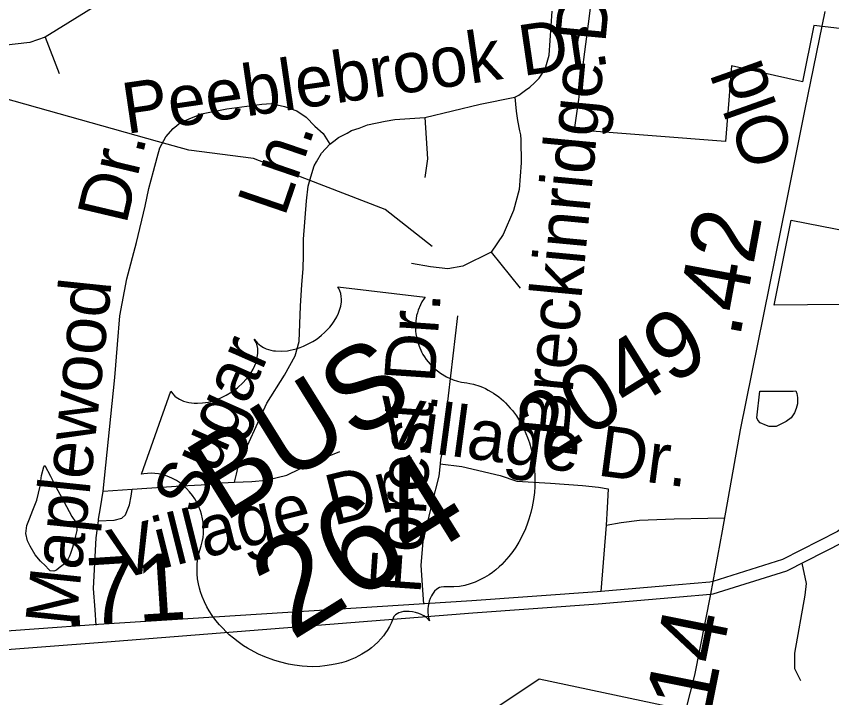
# Model space of a CAD drawing. Extents: x 2001466 to 31450019, y -30647475 to 847247.
# Drawn here: x 2153151 to 2156199, y 745745 to 748291 of the extents above; entities that cross this region are included whole.
import ezdxf

# ---------------------------------------------------------------- set-up
doc = ezdxf.new("R2010")
doc.units = 0
for name, color, linetype in [('Exist Boundary Political City Limit New', 7, 'Continuous'), ('Exist Hydrographic Misc Water Feature', 7, 'Continuous'), ('Exist Road Non-System Type 51', 7, 'Continuous'), ('Exist Road Non-System Type 51 Label', 7, 'Continuous'), ('Exist Road Primary US Divided Attributed', 7, 'Continuous'), ('Exist Road Primary US Mileage Hundredths English Label', 7, 'Continuous'), ('Exist Road Primary US Shield CELL', 7, 'Continuous'), ('Exist Road Primary US Shield Number Label', 7, 'Continuous'), ('Exist Road Secondary Mileage Hundredths English Label', 7, 'Continuous'), ('Exist Road Secondary Type 51 Attributed', 7, 'Continuous'), ('Exist Road Secondary Type 51 Label', 7, 'Continuous'), ('Exist Road Secondary Type 51 Number Label', 7, 'Continuous'), ('Exist Utilities Electrical Transmission Line', 7, 'Continuous'), ('Map Preparation Boundary City Limit Buffer Line', 7, 'Continuous')]:
    doc.layers.add(name, color=color, linetype=linetype)

msp = doc.modelspace()

# ---------------------------------------------------------------- linework, layer by layer
at = {"layer": 'Exist Boundary Political City Limit New'}
for points in [[(2156653.8, 748195.6), (2156132.8, 748257.3), (2156090.5, 748046.9), (2156085.5, 748047.9), (2155825, 748105.6), (2155813.5, 747962.2), (2155812.5, 747948.5), (2155802.5, 747823.7), (2155238.2, 747866.9), (2155253.5, 747980.9), (2155272, 748130), (2155289.8, 748263.6), (2155306, 748392.7)], [(2156483.8, 747216.2), (2155983.8, 747212.1), (2156047.2, 747529.6), (2156436, 747453.1)]]:
    msp.add_lwpolyline(points, dxfattribs=at)
at = {"layer": 'Exist Hydrographic Misc Water Feature'}
for points in [[(2153678.3, 747824), (2153061.2, 747996.6), (2152668.3, 748185.1), (2152451.2, 748215.7), (2152389.5, 748215.4)], [(2154229.1, 747685.7), (2154037.3, 747760), (2153795.3, 747791.3), (2153678.3, 747824)], [(2154705.3, 747431.5), (2154529.2, 747569.5), (2154229.1, 747685.7)], [(2155930.7, 746890.4), (2155989, 746890.9), (2156028.9, 746890.9), (2156050.5, 746890.9), (2156054.8, 746891), (2156064.6, 746891.2), (2156068.9, 746881.2), (2156070.8, 746867.1), (2156071.2, 746843.2), (2156066.9, 746825.2), (2156059.5, 746809.2), (2156047.2, 746791.2), (2156028.9, 746776.9), (2156013.8, 746769.1), (2155991.6, 746758.7), (2155965.2, 746758.6), (2155955.7, 746762.5), (2155931.3, 746772.6), (2155923.3, 746782.4), (2155919, 746790.3), (2155930.7, 746890.4)], [(2153352.8, 746284), (2153349.1, 746274), (2153344.8, 746264.1), (2153334.8, 746249.8), (2153325.5, 746241.9), (2153311.2, 746229.8), (2153301.1, 746221.6), (2153291.3, 746217.4), (2153277.6, 746219.5), (2153271.2, 746225.3), (2153259.3, 746237.3), (2153241.1, 746255.5), (2153221.2, 746279.2), (2153202.7, 746311.2), (2153192.9, 746330.9), (2153186.5, 746359), (2153190.6, 746388.9), (2153200, 746413), (2153211.9, 746445.3), (2153227.9, 746483), (2153239.6, 746535.2), (2153245, 746575.3), (2153253.4, 746607.3), (2153257.3, 746613.2), (2153279, 746573.4), (2153297.4, 746535.7), (2153337.8, 746459.9), (2153358.3, 746421.9), (2153372.1, 746402), (2153376, 746390), (2153376.6, 746370.1), (2153372.3, 746350), (2153368.8, 746333.9), (2153364.7, 746319.9), (2153360.8, 746305.9), (2153352.8, 746284)]]:
    msp.add_lwpolyline(points, dxfattribs=at)
at = {"layer": 'Exist Road Non-System Type 51'}
for p, q in [((2154885, 747962.4), (2155014, 747989.2)), ((2153475.3, 746517.1), (2153583.4, 746524.2)), ((2155736.5, 746415.5), (2155798.3, 746416.8)), ((2155355.5, 746390.3), (2155336.6, 746141.7)), ((2154667.5, 746165.1), (2154673.5, 746094)), ((2153449.5, 746016.4), (2153445.3, 746073.9))]:
    msp.add_line(p, q, dxfattribs=at)
for points in [[(2153745.8, 748461.3), (2153633.4, 748412.3), (2153552.7, 748380.6), (2153454.7, 748334.4), (2153258.7, 748213.3)], [(2153258.7, 748213.3), (2153201, 748193.1), (2153103, 748181.6), (2153007.9, 748190.2), (2152912.8, 748224.8), (2152840.8, 748268.1), (2152783.1, 748320), (2152742.8, 748346), (2152708.2, 748357.5)], [(2155014, 747989.2), (2155029.4, 747996.2), (2155053.9, 748014.7), (2155070.8, 748027), (2155087.7, 748042.3), (2155106.1, 748060), (2155127.6, 748093.8), (2155143, 748146), (2155153.7, 748310.4)], [(2153258.7, 748213.3), (2153310.6, 748077.7)], [(2155014, 747989.2), (2155020.1, 747936.9), (2155024.7, 747901.6), (2155032.4, 747863.2), (2155035.5, 747847.8), (2155037, 747829.4), (2155038.6, 747743.7), (2155030.9, 747643.8), (2155009.4, 747565.4), (2154971, 747476.3), (2154926.5, 747410.3), (2154820.5, 747358), (2154763.7, 747347.3), (2154699.2, 747354.9), (2154628.6, 747367.2)], [(2153687.7, 747799.6), (2153709.2, 747841.1), (2153736.9, 747871.8), (2153764.5, 747894.8), (2153796.7, 747908.7), (2153842.8, 747927.1), (2153938, 747945.5), (2154068.8, 747962.4), (2154104.1, 747965.5), (2154153.3, 747954.8), (2154199.3, 747937.9), (2154234.6, 747914.8), (2154266.9, 747881), (2154297.6, 747853.4), (2154323.1, 747813.4)], [(2154323.1, 747813.4), (2154338.4, 747824.2), (2154355.3, 747838), (2154387.6, 747854.9), (2154404.4, 747864.1), (2154432.1, 747873.3), (2154464.3, 747885.6), (2154530.3, 747899.5), (2154565.7, 747905.6), (2154677.7, 747912.7), (2154885, 747962.4)], [(2154677.7, 747912.7), (2154688.5, 747759), (2154677.7, 747688.3)], [(2153475.3, 746517.1), (2153519.6, 746941.9), (2153529, 747064.4), (2153538.2, 747172), (2153564.3, 747310.2), (2153599.6, 747445.4), (2153632.4, 747581.4), (2153646.3, 747647.5), (2153663.2, 747712), (2153677, 747764.2), (2153687.7, 747799.6)], [(2154252.1, 747691.9), (2154264.4, 747732), (2154273.6, 747747.3), (2154292.1, 747779.6), (2154323.1, 747813.4)], [(2153966.5, 746549.9), (2153974.2, 746580.6), (2153981.9, 746614.4), (2154087.8, 746845.6), (2154153.9, 746950.1), (2154193.8, 747022.3), (2154207.6, 747076.1), (2154213.7, 747208.2), (2154218.4, 747289.3), (2154223, 747347.7), (2154224.5, 747398.4), (2154224.5, 747458.3), (2154235.2, 747601.2), (2154241.4, 747656.5), (2154252.1, 747691.9)], [(2154926.5, 747410.3), (2155034, 747275)], [(2154800.6, 747171.5), (2154756.2, 746798.3), (2154749, 746693), (2154737, 746635.5), (2154735.1, 746618.6)], [(2153966.5, 746549.9), (2154031, 746552.9), (2154085.3, 746557.8), (2154161.8, 746576.9), (2154262.3, 746624.8), (2154360.3, 746665.5)], [(2154735.1, 746618.6), (2154729.9, 746573.3), (2154703.6, 746470.4), (2154670.1, 746329.2), (2154662.9, 746240.6), (2154667.5, 746165.1)], [(2154735.1, 746618.6), (2154816, 746609.2), (2154959.5, 746575.7), (2155021.7, 746554.2), (2155148.4, 746547), (2155266.9, 746537.5), (2155327.2, 746531.8), (2155363, 746526.1), (2155359.3, 746454.5), (2155355.5, 746390.3)], [(2153583.4, 746524.2), (2153767.1, 746536.2), (2153841.3, 746541), (2153919, 746548.3), (2153966.5, 746549.9)], [(2153457.8, 746405.9), (2153516, 746408.2), (2153544.7, 746416.5), (2153559.1, 746428.5), (2153573.4, 746465.6), (2153580.6, 746497.9), (2153583.4, 746524.2)], [(2153457.8, 746405.9), (2153458.6, 746411.8), (2153465.8, 746454.8), (2153475.3, 746517.1)], [(2155355.5, 746390.3), (2155412, 746399.8), (2155480.9, 746408.2), (2155610.1, 746413), (2155736.5, 746415.5)], [(2153445.3, 746073.9), (2153439.5, 746153.3), (2153449, 746342.3), (2153457.8, 746405.9)], [(2156087.9, 746247.8), (2156103.9, 746171.3), (2156098.2, 746127.9), (2156060.5, 745911), (2156060.5, 745854.4), (2156083.1, 745809.2)]]:
    msp.add_lwpolyline(points, dxfattribs=at)
at = {"layer": 'Exist Road Primary US Divided Attributed'}
for points in [[(2162316.3, 749007.1), (2162162.9, 749082.3), (2161879.1, 749216.5), (2161672.8, 749310.3), (2161459.4, 749382.1), (2161277.1, 749426.7), (2161089.8, 749448), (2160905.9, 749439.5), (2160704.5, 749411.9), (2160473.9, 749346.3), (2159910.1, 749128.1), (2158872.5, 748736.3), (2158449.5, 748569.9), (2158156.5, 748402.4), (2157932.6, 748237), (2157701, 748021.8), (2157514.4, 747825.6), (2157040.9, 747240.7), (2156534.3, 746623.9), (2156414.9, 746508.6), (2156220.9, 746366.1), (2156014.9, 746261), (2155754.6, 746179.9)], [(2155745.5, 746132.5), (2155756.6, 746133.5), (2156032, 746219.2), (2156244.6, 746327.7), (2156444, 746474.2), (2156567.4, 746593.4), (2157075.7, 747212.3), (2157548.2, 747795.9), (2157732, 747989.3), (2157995.4, 748199.3), (2158229.8, 748343.8), (2158472.5, 748488.3), (2158889.8, 748694.7), (2159926.1, 749086.1), (2160488.2, 749303.6), (2160713.8, 749367.8), (2160910, 749394.7), (2161088.3, 749402.9), (2161269.2, 749382.3), (2161446.9, 749338.9), (2161656.3, 749268.4), (2161860.2, 749175.7), (2162143.4, 749041.8), (2162302.1, 748964.1)], [(2155754.6, 746179.9), (2155743.3, 746176.4), (2155626.7, 746166.7), (2155322.4, 746140.5), (2154853.8, 746107), (2153457.8, 746018.2), (2152494.7, 745949.4), (2151998.7, 745913.4)], [(2151986.4, 745842.8), (2152511.3, 745879.5), (2153488.6, 745954.2), (2154857, 746062.2), (2155326, 746095.7), (2155630.6, 746121.9), (2155745.5, 746132.5)]]:
    msp.add_lwpolyline(points, dxfattribs=at)
at = {"layer": 'Exist Road Primary US Shield CELL'}
msp.add_lwpolyline([(2153728.5, 746890.4), (2153734.6, 746881.7), (2153743.5, 746872.4), (2153748.6, 746867.9), (2153760.3, 746860.4), (2153776.3, 746853), (2153795.5, 746848), (2153815.2, 746845.4), (2153827.5, 746845.2), (2153847.3, 746846.4), (2153868.7, 746849.9), (2153890.8, 746856.2), (2153912.5, 746864.3), (2153934.9, 746875), (2153955.9, 746887.6), (2153977.3, 746903.2), (2153999.1, 746923.4), (2154008.7, 746933.5), (2154018.8, 746945.9), (2154027.6, 746958.2), (2154036.3, 746973.2), (2154042.5, 746986.5), (2154047, 746997.5), (2154051.7, 747015.8), (2154053.8, 747033), (2154053.6, 747041.9), (2154053.1, 747050.2), (2154049.5, 747066.2), (2154047.2, 747072.8), (2154040.6, 747085.4), (2154047.6, 747075.8), (2154052.6, 747070.1), (2154058.1, 747064.9), (2154064.8, 747060), (2154075.2, 747053.6), (2154085.2, 747049), (2154102.1, 747043.6), (2154111.7, 747041.7), (2154120.1, 747040.7), (2154141.2, 747039.7), (2154164, 747041.7), (2154174.9, 747043.3), (2154185.6, 747045.7), (2154198.8, 747049.2), (2154211.9, 747053.6), (2154224.5, 747058.8), (2154237.1, 747064.3), (2154249.5, 747070.8), (2154259.4, 747076.6), (2154271.2, 747084.1), (2154281.7, 747091.6), (2154292.1, 747099.8), (2154303.2, 747109.6), (2154311.8, 747118), (2154322.8, 747129.7), (2154332, 747141.3), (2154339.6, 747152.3), (2154348.7, 747167.9), (2154355.4, 747181.5), (2154359.4, 747193), (2154363.5, 747207.7), (2154366, 747223.7), (2154366.5, 747234.6), (2154365.4, 747244.8), (2154363.7, 747255.3), (2154360.4, 747265.4), (2154356.7, 747273.6), (2154352.8, 747280.3), (2154679.5, 747242.3), (2154675.5, 747237.2), (2154667.3, 747224), (2154661.3, 747212.5), (2154652.9, 747192.6), (2154650.1, 747182.8), (2154647.4, 747172.7), (2154645.5, 747162.6), (2154644, 747153.3), (2154643.2, 747140.6), (2154643, 747128.2), (2154643.5, 747115.1), (2154644.6, 747104.2), (2154648.9, 747082.5), (2154652.5, 747069.4), (2154656.3, 747058.7), (2154665.9, 747037.6), (2154671, 747027.9), (2154676.7, 747018.7), (2154683.3, 747009.4), (2154690, 747000.7), (2154697.7, 746992), (2154704.5, 746984.5), (2154713.7, 746975.7), (2154725.2, 746966), (2154737.2, 746957.2), (2154759, 746944.5), (2154783.9, 746933.1), (2154799.8, 746928), (2154814.6, 746924.3), (2154835.2, 746921.4), (2154846.5, 746919.5), (2154860.1, 746916.3), (2154883.6, 746909), (2154893.8, 746904.9), (2154904.7, 746900), (2154915.2, 746894.6), (2154926.2, 746888.5), (2154935.3, 746883), (2154954.7, 746869), (2154971.6, 746854.3), (2154980.1, 746846.4), (2154997.5, 746827.5), (2155005.7, 746817.9), (2155020.4, 746798.1), (2155036.2, 746772.8), (2155049.2, 746747.6), (2155062.1, 746716.8), (2155068.8, 746697.7), (2155075.2, 746674.7), (2155080.2, 746654.3), (2155085.7, 746623.2), (2155088.1, 746599.6), (2155089.8, 746571.3), (2155089.9, 746553.7), (2155089.3, 746534.3), (2155087.6, 746511.4), (2155084.6, 746486.3), (2155079.5, 746458.6), (2155074.6, 746437.4), (2155067.1, 746411.6), (2155062.1, 746396.7), (2155054.3, 746376.4), (2155042.5, 746350.5), (2155029.8, 746326.6), (2155018.3, 746307.5), (2155007.4, 746291.7), (2154992.6, 746272.3), (2154965.9, 746243.3), (2154955.7, 746233.6), (2154943.1, 746222.8), (2154930.9, 746213.4), (2154918.7, 746204.8), (2154901.7, 746194.2), (2154884, 746185), (2154866.6, 746177.3), (2154847.8, 746170.4), (2154827.2, 746164.8), (2154807.5, 746161.1), (2154786.6, 746159), (2154749, 746159.2), (2154738.6, 746158.5), (2154733.5, 746156.9), (2154722.8, 746150.9), (2154714.2, 746142.8), (2154706.7, 746132.5), (2154702.6, 746125.5), (2154697.9, 746115.2), (2154694.7, 746106.4), (2154691.7, 746094.7), (2154690.2, 746085.5), (2154689.2, 746078.4), (2154689, 746061.7), (2154689.9, 746054.4), (2154691.6, 746045.2), (2154695.9, 746032.9), (2154683.9, 746044.4), (2154674.3, 746050.9), (2154664.8, 746055.8), (2154655.7, 746059.6), (2154642.7, 746063.6), (2154631.7, 746065.9), (2154619.3, 746067.5), (2154607.2, 746067.3), (2154598, 746066.6), (2154590, 746065), (2154580.9, 746062), (2154574.1, 746058.5), (2154568.9, 746055.1), (2154562.7, 746048.9), (2154557.3, 746035.7), (2154551.9, 746023.4), (2154545.7, 746010.7), (2154537.6, 745996.7), (2154531.3, 745987.1), (2154523.3, 745976.4), (2154513.4, 745964.5), (2154502.2, 745952.7), (2154490.1, 745941.4), (2154479.2, 745931.9), (2154466.9, 745922.6), (2154455.4, 745914.9), (2154443.1, 745907.4), (2154431, 745901.2), (2154417, 745894.1), (2154399, 745886.2), (2154383.4, 745880.8), (2154366.6, 745875.7), (2154348.8, 745871.1), (2154329.2, 745867.3), (2154304, 745863.6), (2154285.7, 745862.1), (2154256.2, 745861), (2154219.6, 745862.8), (2154190.6, 745866.4), (2154168.6, 745870.4), (2154134.6, 745878.6), (2154113.8, 745884.8), (2154079.3, 745897.7), (2154055.9, 745908), (2154039.7, 745916.2), (2154014.9, 745930.1), (2154000.3, 745939.4), (2153980, 745953.6), (2153962.5, 745967.2), (2153946.6, 745980.6), (2153937, 745989.5), (2153921.3, 746005.7), (2153910.5, 746017.4), (2153896.7, 746034.1), (2153883.4, 746052.4), (2153872.1, 746069.9), (2153863.4, 746084.9), (2153854.4, 746103.1), (2153846, 746123.1), (2153839.7, 746140.9), (2153835.9, 746154.1), (2153832, 746170.7), (2153828.7, 746189.6), (2153827, 746208.5), (2153826.4, 746224.8), (2153827, 746243.1), (2153828.7, 746259.3), (2153832.3, 746278.4), (2153837, 746296.7), (2153842.2, 746312), (2153847.1, 746332.3), (2153849.1, 746343.8), (2153850.5, 746359.2), (2153850.8, 746372.8), (2153850.4, 746384.6), (2153849.1, 746401.5), (2153847.1, 746413.6), (2153843, 746431.4), (2153839.1, 746443.3), (2153833.4, 746458.2), (2153827.3, 746471.7), (2153818.2, 746487.7), (2153809.8, 746500.4), (2153798.7, 746514.4), (2153786.9, 746527.1), (2153775.6, 746537.6), (2153761.2, 746548.7), (2153749.6, 746556.2), (2153732.3, 746565.3), (2153714.8, 746572.8), (2153698.4, 746577.7), (2153682.7, 746581.3), (2153668.9, 746582.8), (2153656.2, 746583.6), (2153640.9, 746583.4), (2153626.9, 746582), (2153618.5, 746580.5)], close=True, dxfattribs=at)
at = {"layer": 'Exist Road Secondary Type 51 Attributed'}
for points in [[(2156173.2, 748308.9), (2156098.9, 747944.5), (2156031.9, 747607.3), (2155857.2, 746746.6), (2155789.7, 746368.6), (2155754.6, 746179.9)], [(2155754.6, 746179.9), (2155745.5, 746132.5)], [(2155745.5, 746132.5), (2155686, 745829), (2155636.3, 745634.2), (2155604.9, 745476.1), (2155575.1, 745357.8), (2155528, 745229), (2155388.3, 744916.9), (2155299.4, 744714.8), (2155215.1, 744520.1), (2155003.2, 744098.1), (2154840.5, 743772.4), (2154784, 743634.2), (2154761.5, 743520), (2154737.5, 743388.1), (2154695.6, 743261.4), (2154610.3, 743057.2), (2154517.7, 742841.5)]]:
    msp.add_lwpolyline(points, dxfattribs=at)
at = {"layer": 'Exist Utilities Electrical Transmission Line'}
msp.add_lwpolyline([(2154793.7, 745607.9), (2155105, 745815), (2155586.4, 745713.2)], dxfattribs=at)
at = {"layer": 'Map Preparation Boundary City Limit Buffer Line'}
for points in [[(2156653.8, 748195.6), (2156132.8, 748257.3), (2156090.5, 748046.9), (2156085.5, 748047.9), (2155825, 748105.6), (2155813.5, 747962.2), (2155812.5, 747948.5), (2155802.5, 747823.7), (2155238.2, 747866.9), (2155253.5, 747980.9), (2155272, 748130), (2155289.8, 748263.6), (2155306, 748392.7)], [(2156483.8, 747216.2), (2155983.8, 747212.1), (2156047.2, 747529.6), (2156436, 747453.1)]]:
    msp.add_lwpolyline(points, dxfattribs=at)

# ---------------------------------------------------------------- texts
at = {"layer": 'Exist Road Non-System Type 51 Label'}
for s, rotation, p in [('Breckinridge Dr.', 84.6313, (2155214.2, 746712.4)), ('Peeblebrook Dr.', 8.3044, (2153561.9, 747851.4)), ('Ln.', 71.0925, (2154153.8, 747537.8)), ('Dr.', 76.7041, (2153561.4, 747509.4)), ('Maplewood', 84.0537, (2153372.8, 746007.9)), ('Forest Dr.', 86.1023, (2154661.3, 746129.5)), ('Sugar', 66.0895, (2153828.4, 746421.7)), ('Village Dr.', 352.4279, (2154492.6, 746685.9)), ('Village Dr.', 14.0452, (2153527.2, 746184.6))]:
    msp.add_text(s, height=190, rotation=rotation, dxfattribs=at).set_placement(p)
at = {"layer": 'Exist Road Primary US Mileage Hundredths English Label'}
msp.add_text('.71', height=250, rotation=3.64, dxfattribs=at).set_placement((2153327.3, 746009.9))
at = {"layer": 'Exist Road Primary US Shield Number Label'}
for s, height, p in [('BUS', 310, (2153926.2, 746397.8)), ('264', 360, (2154180.6, 745955.7))]:
    msp.add_text(s, height=height, rotation=31.918, dxfattribs=at).set_placement(p)
at = {"layer": 'Exist Road Secondary Mileage Hundredths English Label'}
for s, rotation, p in [('.42', 79.5036, (2155855.1, 747084.6)), ('.14', 78.7414, (2155728.3, 745590.4))]:
    msp.add_text(s, height=250, rotation=rotation, dxfattribs=at).set_placement(p)
at = {"layer": 'Exist Road Secondary Type 51 Label'}
msp.add_text('Old', height=190, rotation=109.4909, dxfattribs=at).set_placement((2156062, 747769.8))
at = {"layer": 'Exist Road Secondary Type 51 Number Label'}
msp.add_text('2049', height=250, rotation=31.918, dxfattribs=at).set_placement((2155124.5, 746615.9))

doc.saveas('drawing.dxf')
